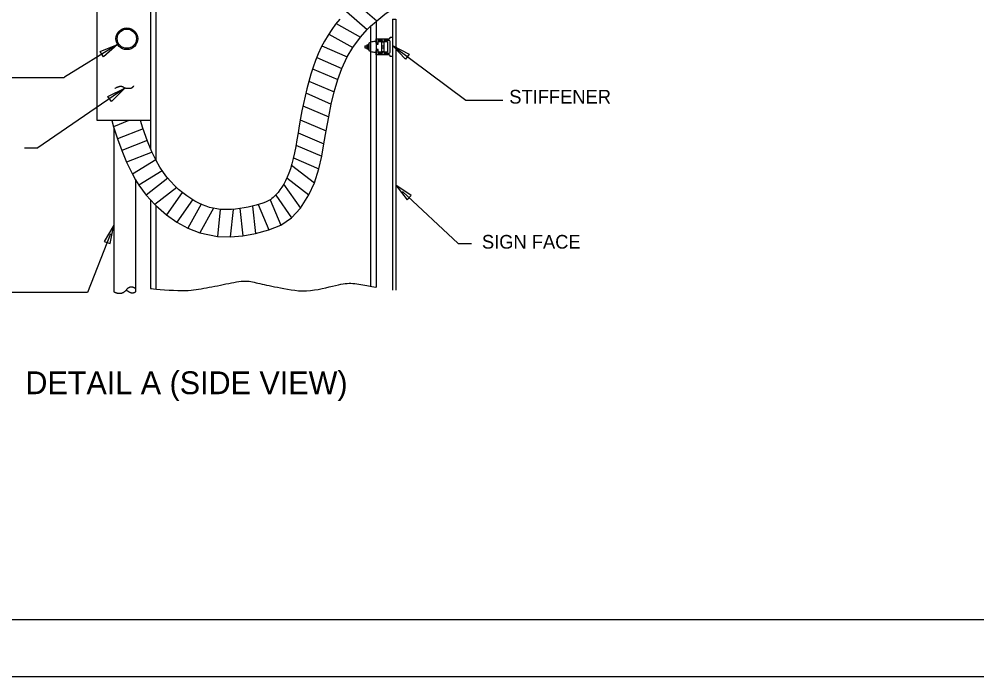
# Model space of a CAD drawing. Extents: x 1299104.6 to 1299141.5, y 239713.3 to 239735.3.
# Drawn here: x 1299110.38 to 1299118.77, y 239713.27 to 239719.04 of the extents above; entities that cross this region are included whole.
import ezdxf

# ---------------------------------------------------------------- set-up
doc = ezdxf.new("R2010")
doc.units = 0
for name, color, linetype in [('DIM TXT', 7, 'Continuous'), ('GS_plotshape_p', 7, 'Continuous'), ('Level 1', 7, 'Continuous'), ('PTEXT', 7, 'Continuous')]:
    doc.layers.add(name, color=color, linetype=linetype)

msp = doc.modelspace()

# ---------------------------------------------------------------- linework, layer by layer
at = {"layer": 'DIM TXT'}
for p, q in [((1299111.2426, 239718.8138), (1299110.7776, 239718.5264)), ((1299113.6517, 239718.804), (1299114.2947, 239718.3268)), ((1299108.9952, 239718.5237), (1299110.7681, 239718.5237)), ((1299111.3049, 239718.4313), (1299110.5449, 239717.9081)), ((1299114.2947, 239718.3268), (1299114.6201, 239718.3268)), ((1299110.4253, 239717.9081), (1299110.5449, 239717.9081)), ((1299113.739, 239717.5259), (1299114.2277, 239717.0695)), ((1299111.1807, 239717.1537), (1299110.9775, 239716.6398)), ((1299114.2277, 239717.0695), (1299114.3429, 239717.0695)), ((1299110.9775, 239716.6398), (1299110.0424, 239716.6398))]:
    msp.add_line(p, q, dxfattribs=at)
for points in [[(1299111.1198, 239718.7048), (1299111.0911, 239718.7505), (1299111.2426, 239718.8138)], [(1299113.7979, 239718.7291), (1299113.7657, 239718.6858), (1299113.6517, 239718.804)], [(1299111.1896, 239718.3144), (1299111.1579, 239718.3581), (1299111.3049, 239718.4313)], [(1299113.7798, 239717.4509), (1299113.8166, 239717.4903), (1299113.6798, 239717.5812)], [(1299111.1258, 239717.0883), (1299111.176, 239717.0684), (1299111.2105, 239717.229)]]:
    msp.add_lwpolyline(points, close=True, dxfattribs=at)
at = {"layer": 'GS_plotshape_p'}
msp.add_lwpolyline([(1299104.6223, 239735.2729), (1299138.6223, 239735.2729), (1299138.6223, 239713.2729), (1299104.6223, 239713.2729)], close=True, dxfattribs=at)
at = {"layer": 'Level 1'}
msp.add_lwpolyline([(1299138.1223, 239713.7729), (1299106.1223, 239713.7729), (1299106.1223, 239734.7729), (1299138.1223, 239734.7729)], close=True, dxfattribs=at)
at = {"layer": 'PTEXT'}
for p, q in [((1299111.5311, 239724.0151), (1299111.5311, 239717.9024)), ((1299111.5786, 239724.0102), (1299111.5786, 239717.7992)), ((1299113.3308, 239719.1794), (1299113.5135, 239719.0209)), ((1299111.0646, 239718.1458), (1299111.0646, 239719.1053)), ((1299113.25, 239719.1017), (1299113.4312, 239718.9444)), ((1299113.1584, 239718.9964), (1299113.3709, 239718.8782)), ((1299113.4601, 239718.9727), (1299113.4601, 239716.6944)), ((1299113.5076, 239719.016), (1299113.5076, 239716.6859)), ((1299113.6517, 239719.0345), (1299113.6517, 239716.66)), ((1299113.6517, 239719.0345), (1299113.6798, 239719.0345)), ((1299113.6798, 239719.0345), (1299113.6798, 239716.6615)), ((1299113.0937, 239718.9046), (1299113.3037, 239718.7878)), ((1299113.4264, 239718.8112), (1299113.4395, 239718.8112)), ((1299113.4264, 239718.8112), (1299113.4264, 239718.774)), ((1299113.4264, 239718.8065), (1299113.4395, 239718.8065)), ((1299113.4395, 239718.8157), (1299113.4438, 239718.8157)), ((1299113.4395, 239718.8157), (1299113.4395, 239718.7695)), ((1299113.5076, 239718.8384), (1299113.5076, 239718.8161)), ((1299113.5076, 239718.8161), (1299113.5267, 239718.8161)), ((1299113.5267, 239718.8394), (1299113.5564, 239718.8394)), ((1299113.5267, 239718.8161), (1299113.5267, 239718.8394)), ((1299113.5564, 239718.8394), (1299113.5564, 239718.7457)), ((1299113.0339, 239718.8001), (1299113.2546, 239718.7047)), ((1299113.4103, 239718.8009), (1299113.4264, 239718.8009)), ((1299113.4103, 239718.8009), (1299113.4103, 239718.7843)), ((1299113.4103, 239718.7843), (1299113.4264, 239718.7843)), ((1299113.4264, 239718.7926), (1299113.4395, 239718.7926)), ((1299113.4264, 239718.7786), (1299113.4395, 239718.7786)), ((1299113.4264, 239718.774), (1299113.4395, 239718.774)), ((1299113.4264, 239718.774), (1299113.4395, 239718.774)), ((1299113.4395, 239718.7695), (1299113.4438, 239718.7695)), ((1299113.5076, 239718.7691), (1299113.5076, 239718.7468)), ((1299113.5267, 239718.7691), (1299113.5076, 239718.7691)), ((1299113.5267, 239718.7457), (1299113.5267, 239718.7691)), ((1299113.5564, 239718.7457), (1299113.5267, 239718.7457)), ((1299113.5564, 239718.8009), (1299113.5789, 239718.8009)), ((1299113.5564, 239718.7843), (1299113.5789, 239718.7843)), ((1299112.9874, 239718.6985), (1299113.2075, 239718.6034)), ((1299112.951, 239718.6006), (1299113.172, 239718.5051)), ((1299112.9181, 239718.4932), (1299113.1406, 239718.397)), ((1299112.8915, 239718.3882), (1299113.1153, 239718.2915)), ((1299112.8672, 239718.2771), (1299113.0924, 239718.1798)), ((1299111.5311, 239718.1458), (1299111.0646, 239718.1458)), ((1299111.3423, 239718.1458), (1299111.2072, 239718.0927)), ((1299112.844, 239718.1539), (1299113.0704, 239718.0561)), ((1299111.2105, 239718.0826), (1299111.2105, 239716.6466)), ((1299111.4654, 239718.0742), (1299111.2422, 239717.9865)), ((1299111.5022, 239717.973), (1299111.279, 239717.8853)), ((1299112.8247, 239718.0406), (1299113.0513, 239717.9427)), ((1299112.806, 239717.9323), (1299113.0315, 239717.8348)), ((1299111.5448, 239717.8698), (1299111.3215, 239717.782)), ((1299111.5768, 239717.8031), (1299111.3719, 239717.6777)), ((1299112.7835, 239717.8203), (1299113.0067, 239717.7239)), ((1299112.7668, 239717.7549), (1299112.9678, 239717.5997)), ((1299111.6334, 239717.7068), (1299111.4288, 239717.5817)), ((1299111.6829, 239717.6412), (1299111.4943, 239717.4928)), ((1299112.7265, 239717.6449), (1299112.9198, 239717.4957)), ((1299111.4006, 239717.6265), (1299111.4006, 239716.6466)), ((1299111.7605, 239717.5602), (1299111.5702, 239717.4104)), ((1299112.6978, 239717.5893), (1299112.8447, 239717.3793)), ((1299111.8089, 239717.5177), (1299111.67, 239717.3219)), ((1299112.6281, 239717.494), (1299112.7675, 239717.295)), ((1299111.5311, 239717.4507), (1299111.5311, 239716.6762)), ((1299111.5786, 239717.4021), (1299111.5786, 239716.6713)), ((1299111.9, 239717.4532), (1299111.761, 239717.2572)), ((1299111.9741, 239717.4138), (1299111.8591, 239717.2029)), ((1299112.0817, 239717.3779), (1299111.9637, 239717.1616)), ((1299112.4246, 239717.3967), (1299112.4503, 239717.1566)), ((1299112.4756, 239717.4109), (1299112.5686, 239717.1889)), ((1299112.5791, 239717.4528), (1299112.6722, 239717.2306)), ((1299112.1429, 239717.3686), (1299112.1172, 239717.1302)), ((1299112.2552, 239717.3686), (1299112.2292, 239717.1271)), ((1299112.3146, 239717.375), (1299112.3401, 239717.1366))]:
    msp.add_line(p, q, dxfattribs=at)
for points in [[(1299113.2075, 239718.6034), (1299113.2546, 239718.7047), (1299113.3037, 239718.7878), (1299113.3709, 239718.8782), (1299113.4312, 239718.9444), (1299113.4601, 239718.9727), (1299113.5076, 239719.016), (1299113.5135, 239719.0209), (1299113.5847, 239719.0779), (1299113.677, 239719.1419), (1299113.7654, 239719.1952), (1299113.865, 239719.2491), (1299113.9624, 239719.2992), (1299114.0629, 239719.352), (1299114.1555, 239719.4048), (1299114.2496, 239719.4658), (1299114.3433, 239719.5368), (1299114.4272, 239719.6107), (1299114.5229, 239719.7131), (1299114.5878, 239719.805), (1299114.6553, 239719.9275), (1299114.7003, 239720.0309), (1299114.7451, 239720.1564), (1299114.7775, 239720.2633)], [(1299113.19, 239719.0357), (1299113.1537, 239718.9906), (1299113.1192, 239718.9434), (1299113.0867, 239718.894), (1299113.0562, 239718.8423), (1299113.0278, 239718.7885), (1299113.0015, 239718.7324), (1299112.9773, 239718.674), (1299112.9553, 239718.6138), (1299112.9353, 239718.5523), (1299112.9171, 239718.4896), (1299112.9005, 239718.426), (1299112.8852, 239718.3616), (1299112.8711, 239718.2967), (1299112.8582, 239718.2315), (1299112.8461, 239718.1663), (1299112.835, 239718.1018), (1299112.8244, 239718.0388), (1299112.8141, 239717.978), (1299112.8038, 239717.9197), (1299112.7932, 239717.8646), (1299112.782, 239717.8133), (1299112.7702, 239717.7664), (1299112.7578, 239717.7244), (1299112.7444, 239717.6866), (1299112.7298, 239717.6517), (1299112.7144, 239717.6195), (1299112.6983, 239717.59), (1299112.6818, 239717.5632), (1299112.6651, 239717.5391), (1299112.6488, 239717.5177), (1299112.6331, 239717.4992), (1299112.619, 239717.4843), (1299112.6067, 239717.4728), (1299112.5957, 239717.4638), (1299112.5847, 239717.4561), (1299112.5726, 239717.4489), (1299112.5577, 239717.4412), (1299112.5389, 239717.433), (1299112.5154, 239717.424), (1299112.4874, 239717.4145), (1299112.4562, 239717.4051), (1299112.4226, 239717.3962), (1299112.3873, 239717.388), (1299112.3508, 239717.3808), (1299112.314, 239717.3749), (1299112.2773, 239717.3704), (1299112.2415, 239717.3674), (1299112.2071, 239717.3662), (1299112.1741, 239717.3666), (1299112.1421, 239717.3687), (1299112.1109, 239717.3725), (1299112.0801, 239717.3782), (1299112.0493, 239717.3859), (1299112.0182, 239717.3958), (1299111.9863, 239717.4082), (1299111.9533, 239717.4233), (1299111.9193, 239717.4415), (1299111.8844, 239717.4627), (1299111.849, 239717.4868), (1299111.8133, 239717.514), (1299111.7777, 239717.5441), (1299111.7424, 239717.5771), (1299111.7078, 239717.6127), (1299111.6752, 239717.6501), (1299111.644, 239717.6907), (1299111.6126, 239717.7385), (1299111.5793, 239717.7977), (1299111.5436, 239717.8722), (1299111.5051, 239717.965), (1299111.4637, 239718.0789), (1299111.442, 239718.1458)], [(1299113.4438, 239718.8186), (1299113.4438, 239718.7666)], [(1299113.4628, 239718.8328), (1299113.4511, 239718.8289)], [(1299113.5076, 239718.8384), (1299113.4971, 239718.8384)], [(1299113.6214, 239718.8491), (1299113.5765, 239718.8491), (1299113.5765, 239718.8346), (1299113.5644, 239718.8346), (1299113.5644, 239718.8491), (1299113.522, 239718.8491), (1299113.522, 239718.8256), (1299113.5076, 239718.8256), (1299113.5076, 239718.8635), (1299113.6214, 239718.8635)], [(1299113.6322, 239718.8743), (1299113.6322, 239718.8781), (1299113.6517, 239718.8781), (1299113.6517, 239718.7071), (1299113.6322, 239718.7071), (1299113.6322, 239718.7109)], [(1299113.6322, 239718.7469), (1299113.6322, 239718.8383)], [(1299113.4511, 239718.7563), (1299113.4628, 239718.7524)], [(1299113.4971, 239718.7468), (1299113.5076, 239718.7468)], [(1299113.6214, 239718.7217), (1299113.5076, 239718.7217), (1299113.5076, 239718.7596), (1299113.522, 239718.7596), (1299113.522, 239718.7361), (1299113.5644, 239718.7361), (1299113.5644, 239718.7506), (1299113.5765, 239718.7506), (1299113.5765, 239718.7361), (1299113.6214, 239718.7361)], [(1299111.1929, 239718.1458), (1299111.2072, 239718.0927), (1299111.2422, 239717.9865), (1299111.279, 239717.8853), (1299111.3215, 239717.782), (1299111.3719, 239717.6777), (1299111.4006, 239717.6265), (1299111.4288, 239717.5817), (1299111.4943, 239717.4928), (1299111.5311, 239717.4507), (1299111.5702, 239717.4104), (1299111.5786, 239717.4021), (1299111.67, 239717.3219), (1299111.761, 239717.2572), (1299111.8591, 239717.2029), (1299111.9637, 239717.1616), (1299112.1172, 239717.1302), (1299112.2292, 239717.1271), (1299112.3401, 239717.1366), (1299112.4503, 239717.1566), (1299112.5686, 239717.1889), (1299112.6722, 239717.2306), (1299112.7675, 239717.295), (1299112.8447, 239717.3793), (1299112.9198, 239717.4957), (1299112.9678, 239717.5997), (1299113.0067, 239717.7239), (1299113.0315, 239717.8348), (1299113.0513, 239717.9427), (1299113.0704, 239718.0561), (1299113.0924, 239718.1798), (1299113.1153, 239718.2915), (1299113.1406, 239718.397), (1299113.172, 239718.5051), (1299113.2075, 239718.6034)], [(1299111.5311, 239716.6762), (1299111.5386, 239716.6753), (1299111.5569, 239716.6734), (1299111.5837, 239716.6709), (1299111.6168, 239716.6679), (1299111.6543, 239716.6648), (1299111.6938, 239716.6619), (1299111.7334, 239716.6595), (1299111.7708, 239716.6578), (1299111.8045, 239716.6571), (1299111.8345, 239716.6574), (1299111.8615, 239716.6585), (1299111.8862, 239716.6603), (1299111.9092, 239716.6628), (1299111.9311, 239716.6658), (1299111.9527, 239716.6692), (1299111.9745, 239716.673), (1299111.9971, 239716.677), (1299112.0204, 239716.6812), (1299112.0444, 239716.6856), (1299112.0688, 239716.6901), (1299112.0934, 239716.6948), (1299112.1183, 239716.6997), (1299112.1431, 239716.7046), (1299112.1678, 239716.7097), (1299112.1922, 239716.7148), (1299112.2161, 239716.7198), (1299112.2396, 239716.7246), (1299112.2623, 239716.7291), (1299112.2843, 239716.733), (1299112.3054, 239716.7362), (1299112.3254, 239716.7386), (1299112.3443, 239716.74), (1299112.362, 239716.7404), (1299112.3786, 239716.7398), (1299112.3946, 239716.7383), (1299112.4101, 239716.736), (1299112.4254, 239716.7332), (1299112.4407, 239716.7299), (1299112.4565, 239716.7263), (1299112.4729, 239716.7225), (1299112.4901, 239716.7185), (1299112.5083, 239716.7145), (1299112.5276, 239716.7103), (1299112.5481, 239716.7059), (1299112.5699, 239716.7013), (1299112.593, 239716.6964), (1299112.6176, 239716.6913), (1299112.6438, 239716.6857), (1299112.6715, 239716.6799), (1299112.7007, 239716.674), (1299112.7313, 239716.6684), (1299112.763, 239716.6634), (1299112.7956, 239716.6593), (1299112.8291, 239716.6563), (1299112.8632, 239716.655), (1299112.8977, 239716.6554), (1299112.9325, 239716.6579), (1299112.9673, 239716.6622), (1299113.0016, 239716.6679), (1299113.0351, 239716.6745), (1299113.0674, 239716.6816), (1299113.0981, 239716.689), (1299113.1268, 239716.6961), (1299113.1533, 239716.7025), (1299113.1772, 239716.708), (1299113.1988, 239716.7124), (1299113.2185, 239716.7159), (1299113.2368, 239716.7185), (1299113.2541, 239716.7201), (1299113.2709, 239716.7209), (1299113.2874, 239716.7209), (1299113.3042, 239716.7201), (1299113.3216, 239716.7185), (1299113.3394, 239716.7164), (1299113.3574, 239716.7137), (1299113.3753, 239716.7107), (1299113.393, 239716.7075), (1299113.4102, 239716.7042), (1299113.4265, 239716.701), (1299113.4419, 239716.6979), (1299113.4563, 239716.6951), (1299113.471, 239716.6924), (1299113.4873, 239716.6895), (1299113.5066, 239716.6861), (1299113.5076, 239716.6859)]]:
    msp.add_lwpolyline(points, dxfattribs=at)
msp.add_lwpolyline([(1299113.5789, 239718.7457), (1299113.5789, 239718.8394), (1299113.6085, 239718.8394), (1299113.6085, 239718.7457)], close=True, dxfattribs=at)
for radius in [0.095, 0.0842]:
    msp.add_circle((1299111.3235, 239718.8637), radius, dxfattribs=at)
for centre, radius, start, end in [((1299113.4546, 239718.8186), 0.0108, 108.51102, 180), ((1299113.4971, 239718.7304), 0.108, 90, 108.51102), ((1299113.6214, 239718.8743), 0.0108, 270, 360), ((1299113.6214, 239718.8383), 0.0108, 360, 90), ((1299113.4546, 239718.7666), 0.0108, 180, 251.48898), ((1299113.4971, 239718.8548), 0.108, 251.48898, 270), ((1299113.6214, 239718.7469), 0.0108, 270, 0), ((1299113.6214, 239718.7109), 0.0108, 360, 90), ((1299110.7681, 239718.5417), 0.018, 270, 301.71114)]:
    msp.add_arc(centre, radius, start, end, dxfattribs=at)
for points in [[(1299111.2169, 239718.4292), (1299111.2521, 239718.4471), (1299111.2839, 239718.4474), (1299111.3016, 239718.4334), (1299111.3264, 239718.4301), (1299111.3653, 239718.4304), (1299111.3793, 239718.4446), (1299111.3863, 239718.4517)], [(1299111.2105, 239716.6466), (1299111.2316, 239716.6367), (1299111.2529, 239716.6322), (1299111.2831, 239716.6349), (1299111.3088, 239716.6508), (1299111.339, 239716.6854), (1299111.363, 239716.6925), (1299111.3887, 239716.6846), (1299111.4006, 239716.6757)], [(1299111.4006, 239716.6466), (1299111.3896, 239716.6358), (1299111.3639, 239716.634), (1299111.3461, 239716.6429), (1299111.317, 239716.6602)]]:
    msp.add_open_spline(points, degree=2, dxfattribs=at)

# ---------------------------------------------------------------- texts
at = {"layer": 'DIM TXT'}
for s, height, p in [('STIFFENER', 0.12, (1299114.6751, 239718.2956)), ('SIGN FACE', 0.12, (1299114.4356, 239717.0246)), ('DETAIL A (SIDE VIEW)', 0.2, (1299110.4347, 239715.7494))]:
    msp.add_text(s, height=height, dxfattribs=at).set_placement(p)

doc.saveas('drawing.dxf')
